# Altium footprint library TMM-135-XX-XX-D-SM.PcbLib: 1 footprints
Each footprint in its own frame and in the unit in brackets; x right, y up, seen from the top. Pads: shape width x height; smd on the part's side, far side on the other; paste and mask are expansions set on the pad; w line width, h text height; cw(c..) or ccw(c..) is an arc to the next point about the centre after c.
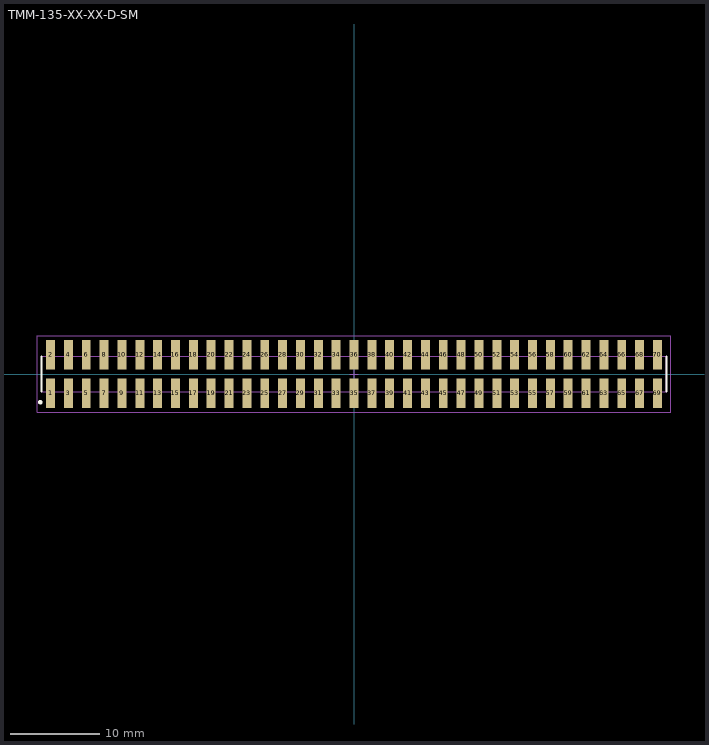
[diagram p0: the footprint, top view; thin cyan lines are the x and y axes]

## TMM-135-XX-XX-D-SM [mm] "2.00mm pitch, 70 pin, terminal strip; double row, SMT"
height 2.77
pads (70):
  rect 1x3.3 smd mask+0: 1(-34,-2.15) 2(-34,2.15) 3(-32,-2.15) 4(-32,2.15) 5(-30,-2.15) 6(-30,2.15) 7(-28,-2.15) 8(-28,2.15) 9(-26,-2.15) 10(-26,2.15) 11(-24,-2.15) 12(-24,2.15) 13(-22,-2.15) 14(-22,2.15) 15(-20,-2.15) 16(-20,2.15) 17(-18,-2.15) 18(-18,2.15) 19(-16,-2.15) 20(-16,2.15) 21(-14,-2.15) 22(-14,2.15) 23(-12,-2.15) 24(-12,2.15) 25(-10,-2.15) 26(-10,2.15) 27(-8,-2.15) 28(-8,2.15) 29(-6,-2.15) 30(-6,2.15) 31(-4,-2.15) 32(-4,2.15) 33(-2,-2.15) 34(-2,2.15) 35(0,-2.15) 36(0,2.15) 37(2,-2.15) 38(2,2.15) 39(4,-2.15) 40(4,2.15) 41(6,-2.15) 42(6,2.15) 43(8,-2.15) 44(8,2.15) 45(10,-2.15) 46(10,2.15) 47(12,-2.15) 48(12,2.15) 49(14,-2.15) 50(14,2.15) 51(16,-2.15) 52(16,2.15) 53(18,-2.15) 54(18,2.15) 55(20,-2.15) 56(20,2.15) 57(22,-2.15) 58(22,2.15) 59(24,-2.15) 60(24,2.15) 61(26,-2.15) 62(26,2.15) 63(28,-2.15) 64(28,2.15) 65(30,-2.15) 66(30,2.15) 67(32,-2.15) 68(32,2.15) 69(34,-2.15) 70(34,2.15)
Top Overlay:
  circle w0.25: c-35.15,-3.15 r0.125
  lines w0.2: -35,-2 -35,2 ; 35,-2 35,2
Mechanical 12:
  lines w0.001: -35,-2 35,-2 35,2 -35,2 -35,-2
Mechanical 13:
  lines w0.1: -35,-2 35,-2 35,2 -35,2 -35,-2
  text ".Designator" at 0,-0.127 h1.52
Mechanical 15:
  lines w0.05: -0.5,0 0.5,0 ; 0,-0.5 0,0.5 ; -35.5,-4.3 35.5,-4.3 35.5,4.3 -35.5,4.3 -35.5,-4.3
